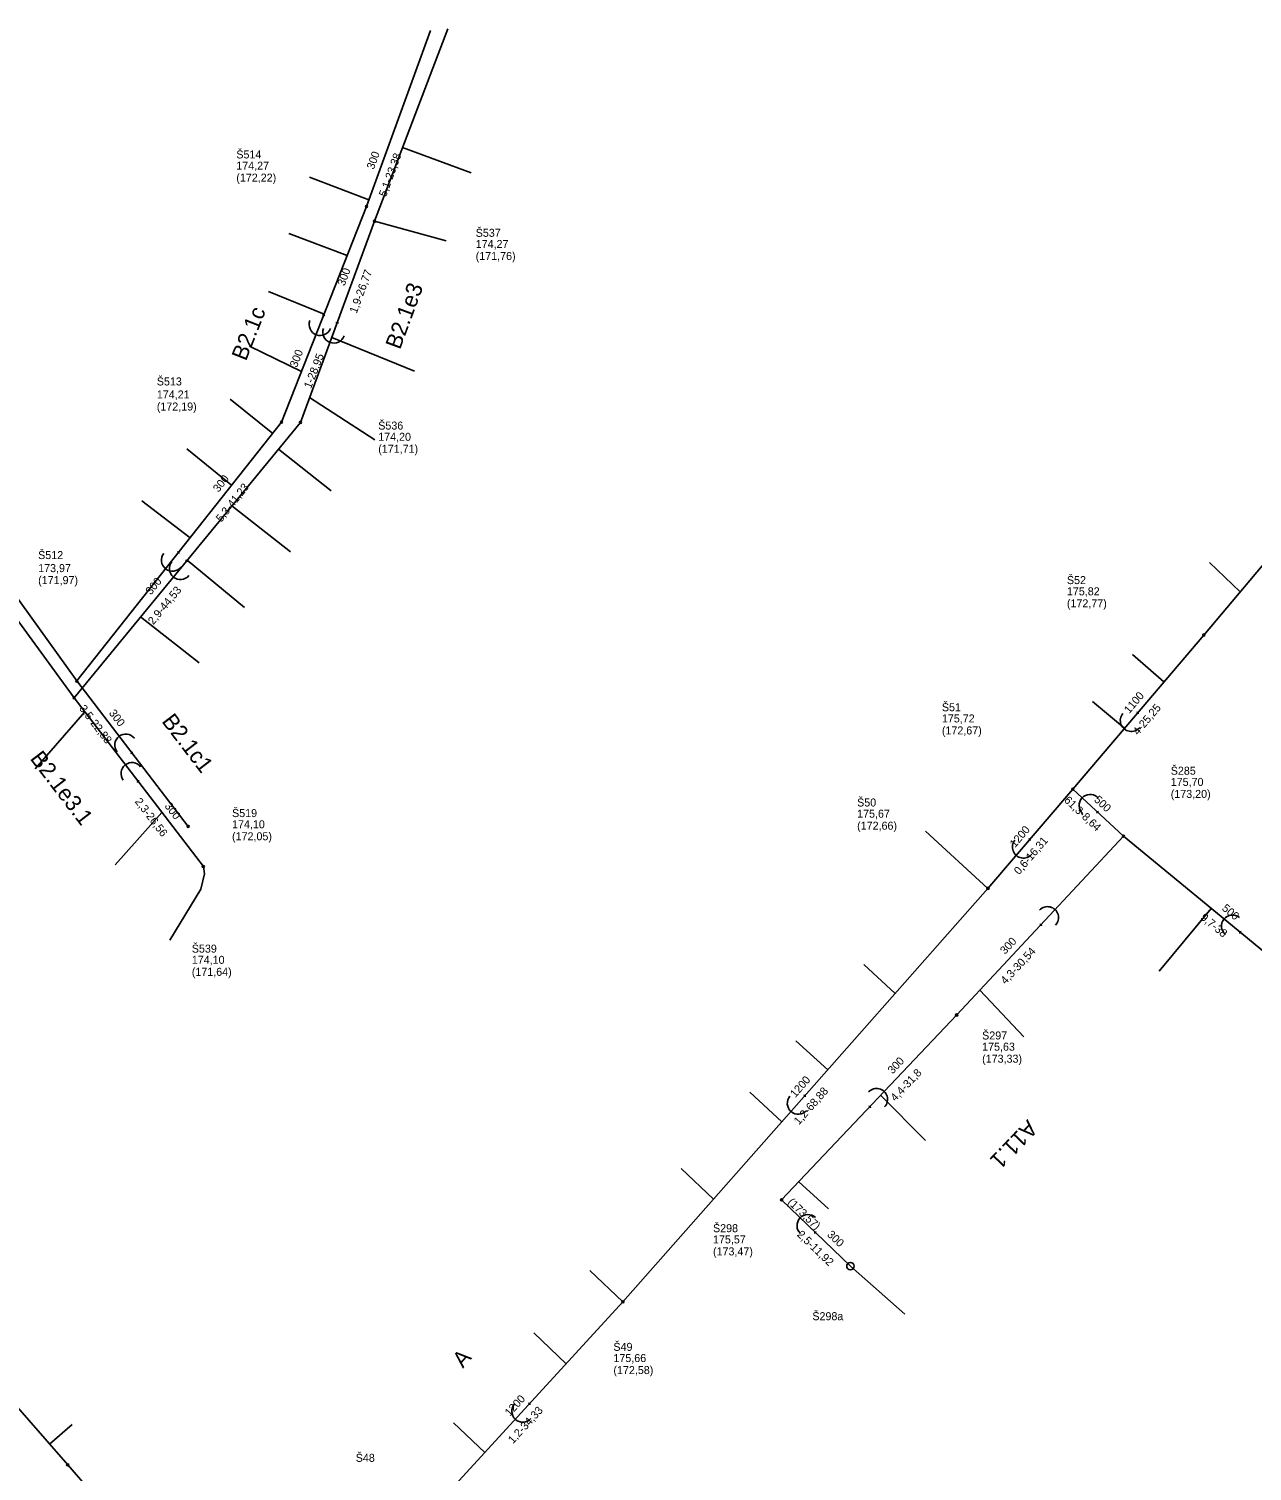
# Model space of a CAD drawing. Extents: x -548529 to -543591, y -1201432 to -1192608.
# Drawn here: x -544287.5 to -544134.8, y -1192840.3 to -1192660.1 of the extents above; entities that cross this region are included whole.
import ezdxf

# ---------------------------------------------------------------- set-up
doc = ezdxf.new("R2010")
doc.units = 0
for name, color, linetype in [('C3D_Bod-Značky', 7, 'Continuous'), ('C3D_Koridor', 7, 'Continuous'), ('C3D_Křižovatka', 7, 'Continuous'), ('C3D_Netisknutelná', 7, 'Continuous'), ('C3D_PP-zobrazeni v PR', 7, 'Continuous'), ('C3D_PR-Popisek', 7, 'Continuous'), ('C3D_SPR-Popisek', 7, 'Continuous'), ('C3D_Tlakove_potrubi_Popis', 7, 'Continuous'), ('C3D_ZPR-Formaty', 7, 'Continuous')]:
    doc.layers.add(name, color=color, linetype=linetype)

# ---------------------------------------------------------------- blocks, each defined once
blk = doc.blocks.new('100')
at = {"layer": 'Defpoints'}
blk.add_circle((0, 0), 0.127, dxfattribs=at)
blk = doc.blocks.new('101')
at = {"layer": 'Defpoints'}
blk.add_circle((0, 0), 0.463, dxfattribs=at)
blk = doc.blocks.new('86')
at = {"layer": 'Defpoints'}
blk.add_lwpolyline([(0.08, 0.14), (0.19, 0), (0.08, -0.14)], dxfattribs=at)
blk.add_arc((1.37, 0), 1.37, 270, 90, dxfattribs=at)
blk = doc.blocks.new('91')
at = {"layer": 'Defpoints'}
blk.add_lwpolyline([(0.08, 0.14), (0.19, 0), (0.08, -0.14)], dxfattribs=at)
blk.add_arc((1.37, 0), 1.37, 270, 90, dxfattribs=at)

msp = doc.modelspace()

# ---------------------------------------------------------------- linework, layer by layer
at = {"layer": 'C3D_Bod-Značky'}
for points in [[(-544235.186, -1192660.072), (-544244.342, -1192684.114)], [(-544237.361, -1192660.29), (-544245.343, -1192682.261)], [(-544245.343, -1192682.261), (-544255.95, -1192709.202)], [(-544244.342, -1192684.114), (-544253.592, -1192709.234)], [(-544103.721, -1192691.738), (-544140.8, -1192735.8)], [(-544281.526, -1192741.543), (-544305.076, -1192708.764)], [(-544281.861, -1192743.64), (-544306.195, -1192710.243)], [(-544253.592, -1192709.234), (-544281.861, -1192743.64)], [(-544255.95, -1192709.202), (-544281.526, -1192741.543)], [(-544140.8, -1192735.8), (-544157.14, -1192755.053)], [(-544267.615, -1192759.705), (-544281.526, -1192741.543)], [(-544265.72, -1192764.728), (-544281.861, -1192743.64)], [(-544157.14, -1192755.053), (-544167.744, -1192767.451)], [(-544150.823, -1192760.942), (-544157.14, -1192755.053)], [(-544171.655, -1192783.27), (-544150.823, -1192760.942)], [(-544121.491, -1192785.096), (-544150.823, -1192760.942)], [(-544167.744, -1192767.451), (-544213.325, -1192819.098)], [(-544193.51, -1192806.375), (-544171.655, -1192783.27)], [(-544184.924, -1192814.649), (-544193.51, -1192806.375)], [(-544304.76, -1192814.21), (-544282.66, -1192839.46)], [(-544213.325, -1192819.098), (-544236.511, -1192844.411)], [(-544282.66, -1192839.46), (-544257.75, -1192868.27)]]:
    msp.add_lwpolyline(points, dxfattribs=at)
at = {"layer": 'C3D_Koridor'}
for points in [[(-544240.837, -1192674.911), (-544232.275, -1192678.058)], [(-544245.049, -1192681.451), (-544252.467, -1192678.617)], [(-544244.342, -1192684.114), (-544235.402, -1192686.562)], [(-544247.748, -1192688.37), (-544255.048, -1192685.644)], [(-544250.646, -1192695.732), (-544257.592, -1192692.885)], [(-544253.452, -1192702.859), (-544259.966, -1192699.701)], [(-544249.681, -1192698.612), (-544239.341, -1192702.834)], [(-544257.061, -1192710.606), (-544262.389, -1192706.327)], [(-544252.455, -1192706.146), (-544244.3, -1192711.434)], [(-544262.195, -1192717.099), (-544267.764, -1192712.539)], [(-544256.341, -1192712.58), (-544249.761, -1192717.789)], [(-544267.379, -1192723.654), (-544273.385, -1192719.018)], [(-544262.145, -1192719.643), (-544254.836, -1192725.389)], [(-544267.726, -1192726.437), (-544260.591, -1192732.349)], [(-544136.258, -1192730.403), (-544140.074, -1192726.743)], [(-544273.548, -1192733.523), (-544266.229, -1192739.276)], [(-544145.774, -1192741.661), (-544149.681, -1192738.222)], [(-544150.678, -1192747.439), (-544154.705, -1192744.11)], [(-544280.532, -1192745.376), (-544286.732, -1192752.506)], [(-544270.893, -1192757.97), (-544276.745, -1192764.514)], [(-544167.744, -1192767.451), (-544175.544, -1192760.31)], [(-544265.72, -1192764.728), (-544265.583, -1192765.648), (-544266.032, -1192767.545), (-544269.904, -1192773.919)], [(-544139.868, -1192769.963), (-544146.351, -1192777.787)], [(-544179.333, -1192780.582), (-544183.228, -1192776.96)], [(-544168.78, -1192780.188), (-544163.283, -1192786.009)], [(-544187.743, -1192790.112), (-544191.745, -1192786.483)], [(-544193.477, -1192796.608), (-544197.481, -1192792.912)], [(-544181.148, -1192793.306), (-544175.541, -1192798.96)], [(-544202.017, -1192806.285), (-544206.056, -1192802.443)], [(-544191.354, -1192804.095), (-544187.643, -1192807.474)], [(-544184.924, -1192814.649), (-544178.146, -1192820.629)], [(-544213.325, -1192819.098), (-544217.467, -1192815.202)], [(-544220.428, -1192826.852), (-544224.445, -1192822.978)], [(-544284.916, -1192836.882), (-544282.09, -1192834.433)], [(-544230.586, -1192837.943), (-544234.5, -1192834.2)]]:
    msp.add_lwpolyline(points, dxfattribs=at)

# ---------------------------------------------------------------- block references
at = {"layer": 'C3D_PP-zobrazeni v PR'}
for name, p, xscale, yscale, rotation in [('100', (-544245.343, -1192682.261), 0.9999999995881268, 0.9999999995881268, -110.00000065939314), ('100', (-544244.342, -1192684.114), 0.9999999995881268, 0.9999999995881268, -110.00000065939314), ('100', (-544255.95, -1192709.202), 1.0000000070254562, 1.0000000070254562, -118.99999892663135), ('100', (-544253.592, -1192709.234), 1.0000000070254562, 1.0000000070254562, -118.99999892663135), ('100', (-544140.8, -1192735.8), 1.0000000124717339, 1.0000000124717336, -130.0000013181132), ('100', (-544281.526, -1192741.543), 0.9999999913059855, 0.9999999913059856, 127.00000193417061), ('100', (-544281.861, -1192743.64), 0.9999999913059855, 0.9999999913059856, 127.00000193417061), ('100', (-544157.14, -1192755.053), 1.0000000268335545, 1.0000000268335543, 93.99999971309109), ('100', (-544267.615, -1192759.705), 1.000000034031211, 1.0000000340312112, -51.999999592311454), ('100', (-544150.823, -1192760.942), 1.0000000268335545, 1.0000000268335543, -176.00000028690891), ('100', (-544265.72, -1192764.728), 1.000000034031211, 1.0000000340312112, -51.999999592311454), ('100', (-544167.744, -1192767.451), 1.0000000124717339, 1.0000000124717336, -130.0000013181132), ('100', (-544171.655, -1192783.27), 1.00000000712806, 1.00000000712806, -133.00000056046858), ('100', (-544193.51, -1192806.375), 1.00000001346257, 1.0000000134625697, 91.99999990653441), ('101', (-544184.924, -1192814.649), 1.00000000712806, 1.00000000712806, -43.0000005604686), ('100', (-544213.325, -1192819.098), 1.0000000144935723, 1.0000000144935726, -130.99999910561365), ('100', (-544282.66, -1192839.46), 1.0000000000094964, 1.0000000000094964, 132.0000013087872)]:
    msp.add_blockref(name, p, dxfattribs=dict(at, xscale=xscale, yscale=yscale, rotation=rotation))
at = {"layer": 'C3D_SPR-Popisek'}
for name, p, xscale, yscale, rotation in [('86', (-544250.646, -1192695.732), 0.9999999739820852, 0.9999999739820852, -111.00000058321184), ('86', (-544248.967, -1192696.674), 0.9999999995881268, 0.9999999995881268, -110.00000065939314), ('86', (-544268.738, -1192725.372), 1.000000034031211, 1.0000000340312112, -128.00000040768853), ('86', (-544267.726, -1192726.437), 1.000000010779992, 1.0000000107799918, -128.99999891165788), ('91', (-544148.97, -1192745.426), 1.0000000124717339, 1.0000000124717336, -130.0000013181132), ('86', (-544274.57, -1192750.624), 1.000000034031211, 1.0000000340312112, 128.00000040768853), ('86', (-544273.79, -1192754.184), 1.000000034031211, 1.0000000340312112, 128.00000040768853), ('91', (-544153.982, -1192757.998), 1.0000000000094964, 1.0000000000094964, 137.9999986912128), ('91', (-544162.442, -1192761.252), 1.0000000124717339, 1.0000000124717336, -130.0000013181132), ('91', (-544161.239, -1192772.106), 1.00000000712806, 1.00000000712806, 46.99999943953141), ('91', (-544136.157, -1192773.019), 1.000000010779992, 1.0000000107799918, 141.00000108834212), ('91', (-544190.534, -1192793.274), 1.0000000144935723, 1.0000000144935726, -130.99999910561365), ('91', (-544182.582, -1192794.822), 1.00000000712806, 1.00000000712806, 46.99999943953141), ('91', (-544189.217, -1192810.512), 1.00000000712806, 1.00000000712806, 136.99999943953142), ('91', (-544224.918, -1192831.754), 1.0000000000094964, 1.0000000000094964, -132.0000013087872)]:
    msp.add_blockref(name, p, dxfattribs=dict(at, xscale=xscale, yscale=yscale, rotation=rotation))

# ---------------------------------------------------------------- texts
at = {"layer": 'C3D_Křižovatka'}
for s, p in [('Š514', (-544261.603, -1192676.261)), ('Š537', (-544231.712, -1192686.054)), ('Š513', (-544271.53, -1192704.622)), ('Š536', (-544243.882, -1192710.134)), ('Š512', (-544286.346, -1192726.313)), ('Š52', (-544157.89, -1192729.44)), ('Š51', (-544173.5, -1192745.323)), ('Š285', (-544144.923, -1192753.252)), ('Š519', (-544262.135, -1192758.545)), ('Š50', (-544184.084, -1192757.221)), ('Š539', (-544267.16, -1192775.478)), ('Š297', (-544168.475, -1192786.33)), ('Š298', (-544202.08, -1192810.405)), ('Š298a', (-544189.674, -1192821.399)), ('Š49', (-544214.515, -1192825.228)), ('Š48', (-544246.691, -1192839.091))]:
    msp.add_text(s, height=1, dxfattribs=at).set_placement(p)
at = {"layer": 'C3D_Netisknutelná'}
for s, rotation, p in [('B2.1e3', 69.78, (-544241.166, -1192700.231)), ('B2.1c', 68.51, (-544260.396, -1192701.656)), ('B2.1c1', 307.45, (-544270.997, -1192746.596)), ('B2.1e3.1', 307.43, (-544287.441, -1192751.246)), ('A11.1', 226.2, (-544162.801, -1192796.246)), ('A', 48.57, (-544233.305, -1192827.47))]:
    msp.add_text(s, height=2, rotation=rotation, dxfattribs=at).set_placement(p)
at = {"layer": 'C3D_PR-Popisek'}
for s, rotation, p in [('300', 70.03, (-544244.432, -1192677.705)), ('300', 69.78, (-544248.089, -1192692.266)), ('300', 68.51, (-544254.05, -1192702.455)), ('300', 51.66, (-544263.831, -1192718.042)), ('300', 50.59, (-544272.264, -1192730.85)), ('1100', 49.68, (-544150.107, -1192745.689)), ('300', 307.45, (-544277.565, -1192745.564)), ('300', 307.43, (-544270.616, -1192757.18)), ('500', 317.01, (-544154.578, -1192756.481)), ('1200', 49.46, (-544164.364, -1192762.428)), ('500', 320.53, (-544138.615, -1192770.082)), ('300', 46.99, (-544165.615, -1192775.767)), ('300', 46.59, (-544179.653, -1192790.713)), ('1200', 48.57, (-544191.805, -1192793.662)), ('300', 316.06, (-544187.909, -1192810.797)), ('1200', 47.51, (-544227.454, -1192833.483))]:
    msp.add_text(s, height=1, rotation=rotation, dxfattribs=at).set_placement(p)
at = {"layer": 'C3D_Tlakove_potrubi_Popis'}
for s, p in [('(172,22)', (-544261.603, -1192679.161)), ('174,27 ', (-544261.603, -1192677.661)), ('174,27 ', (-544231.712, -1192687.454)), ('(171,76)', (-544231.712, -1192688.954)), ('(172,19)', (-544271.53, -1192707.752)), ('174,21 ', (-544271.53, -1192706.252)), ('174,20 ', (-544243.882, -1192711.534)), ('(171,71)', (-544243.882, -1192713.034)), ('(171,97)', (-544286.346, -1192729.443)), ('173,97 ', (-544286.346, -1192727.943)), ('175,82 ', (-544157.89, -1192730.84)), ('(172,77)', (-544157.89, -1192732.34)), ('175,72 ', (-544173.5, -1192746.723)), ('(172,67)', (-544173.5, -1192748.223)), ('175,70 ', (-544144.923, -1192754.652)), ('(173,20)', (-544144.923, -1192756.152)), ('174,10 ', (-544262.135, -1192759.945)), ('(172,66)', (-544184.084, -1192760.121)), ('175,67 ', (-544184.084, -1192758.621)), ('(172,05)', (-544262.135, -1192761.445)), ('174,10 ', (-544267.16, -1192776.878)), ('(171,64)', (-544267.16, -1192778.378)), ('175,63 ', (-544168.475, -1192787.73)), ('(173,33)', (-544168.475, -1192789.23)), ('175,57 ', (-544202.08, -1192811.805)), ('(173,47)', (-544202.08, -1192813.305)), ('175,66 ', (-544214.515, -1192826.628)), ('(172,58)', (-544214.515, -1192828.128))]:
    msp.add_text(s, height=1, dxfattribs=at).set_placement(p)
at = {"layer": 'C3D_ZPR-Formaty'}
for s, rotation, p in [('5,1-23,38', 70.03, (-544242.908, -1192681.13)), ('1,9-26,77', 69.78, (-544246.579, -1192695.693)), ('1-28,95', 68.51, (-544252.286, -1192705.083)), ('5,3-41,23', 51.66, (-544263.468, -1192721.768)), ('2,9-44,53', 50.59, (-544271.966, -1192734.585)), ('3,5-22,88', 307.45, (-544281.278, -1192745.001)), ('4-25,25', 49.68, (-544149.003, -1192748.394)), ('2,3-26,56', 307.43, (-544274.328, -1192756.617)), ('61,3-8,64', 317.01, (-544158.328, -1192756.544)), ('0,6-16,31', 49.46, (-544163.852, -1192765.818)), ('9,7-38', 320.53, (-544141.307, -1192771.235)), ('4,3-30,54', 46.99, (-544165.553, -1192779.516)), ('4,4-31,8', 46.59, (-544179.312, -1192794.13)), ('1,2-68,88', 48.57, (-544191.354, -1192797.066)), ('  (173,57)   ', 316.06, (-544193.371, -1192806.231)), ('2,5-11,92', 316.06, (-544191.665, -1192810.792)), ('1,2-34,33', 47.51, (-544227.052, -1192836.898))]:
    msp.add_text(s, height=1, rotation=rotation, dxfattribs=at).set_placement(p)

doc.saveas('drawing.dxf')
